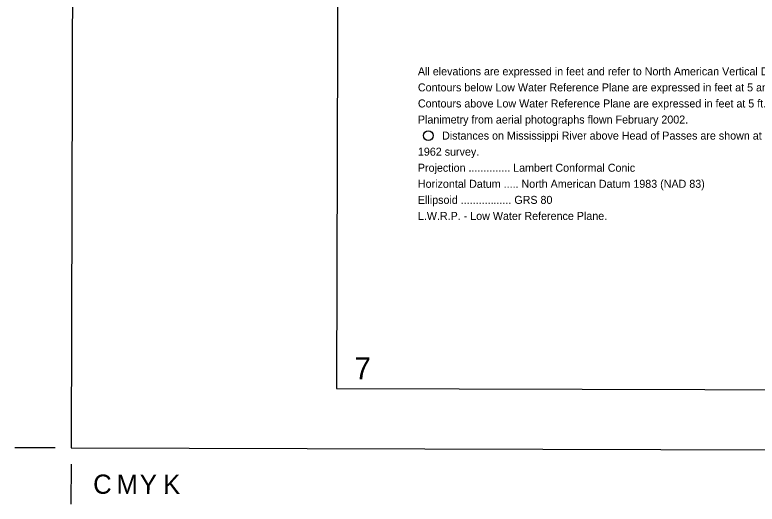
# Model space of a CAD drawing. Extents: x 3161665 to 3199565, y 885729 to 911164.
# Drawn here: x 3161665 to 3169358, y 885830 to 890907 of the extents above; entities that cross this region are included whole.
import ezdxf

# ---------------------------------------------------------------- set-up
doc = ezdxf.new("R2010")
doc.units = 0
for name, color, linetype in [('G-ANNO-NPLT', 7, 'Continuous'), ('V-ANNO-DIMS', 7, 'Continuous'), ('V-ANNO-NOTE', 7, 'Continuous'), ('V-ANNO-SYMB', 7, 'Continuous'), ('V-ANNO-TEXT', 7, 'Continuous')]:
    doc.layers.add(name, color=color, linetype=linetype)

msp = doc.modelspace()

# ---------------------------------------------------------------- linework, layer by layer
at = {"layer": 'G-ANNO-NPLT'}
msp.add_lwpolyline([(3162248.3, 886413.8), (3198914.8, 886312.5), (3198981.6, 910479), (3162315.1, 910580.4)], close=True, dxfattribs=at)
at = {"layer": 'V-ANNO-DIMS'}
for p, q in [((3162081.7, 886414.2), (3161665, 886415.4)), ((3162247.9, 886247.1), (3162246.7, 885830.5))]:
    msp.add_line(p, q, dxfattribs=at)
at = {"layer": 'V-ANNO-NOTE'}
msp.add_circle((3165950.5, 889653.9), 50, dxfattribs=at)
at = {"layer": 'V-ANNO-SYMB'}
msp.add_lwpolyline([(3165000.2, 887031.2), (3198083.2, 886939.8), (3198146.6, 909856.3), (3165063.5, 909947.7), (3165000.2, 887031.2)], dxfattribs=at)

# ---------------------------------------------------------------- texts
at = {"layer": 'V-ANNO-DIMS'}
for s, p in [('C', (3162476, 885938.5)), ('M', (3162717.6, 885937.9)), ('Y', (3162959.3, 885937.2)), ('K', (3163201, 885936.5))]:
    msp.add_text(s, height=199.3, rotation=359.84167, dxfattribs=at).set_placement(p)
at = {"layer": 'V-ANNO-NOTE'}
for s, rotation, p in [('All elevations are expressed in feet and refer to North American Vertical Datum of 1988.', 0.00001, (3165842.3, 890279.2)), ('Contours below Low Water Reference Plane are expressed in feet at 5 and 10 ft. intervals.', 0.00001, (3165842.3, 890112.5)), ('Contours above Low Water Reference Plane are expressed in feet at 5 ft. intervals.', 0.00001, (3165842.3, 889945.8)), ('Planimetry from aerial photographs flown February 2002.', 0.00001, (3165842.3, 889779.1)), ('Distances on Mississippi River above Head of Passes are shown at 1 mile intervals,', 0.00001, (3166092.5, 889612.4)), ('1962 survey.', 0.00001, (3165842.3, 889445.7)), ('Projection .............. Lambert Conformal Conic', 359.99998, (3165842.3, 889279)), ('Horizontal Datum ..... North American Datum 1983 (NAD 83)', 359.99998, (3165842.3, 889112.3)), ('Ellipsoid ................. GRS 80', 359.99998, (3165842.3, 888945.6)), ('L.W.R.P. - Low Water Reference Plane.', 359.99998, (3165842.3, 888778.9))]:
    msp.add_text(s, height=83, rotation=rotation, dxfattribs=at).set_placement(p)
at = {"layer": 'V-ANNO-TEXT'}
msp.add_text('7', height=230, rotation=359.84167, dxfattribs=at).set_placement((3165183.9, 887124.1))

doc.saveas('drawing.dxf')
